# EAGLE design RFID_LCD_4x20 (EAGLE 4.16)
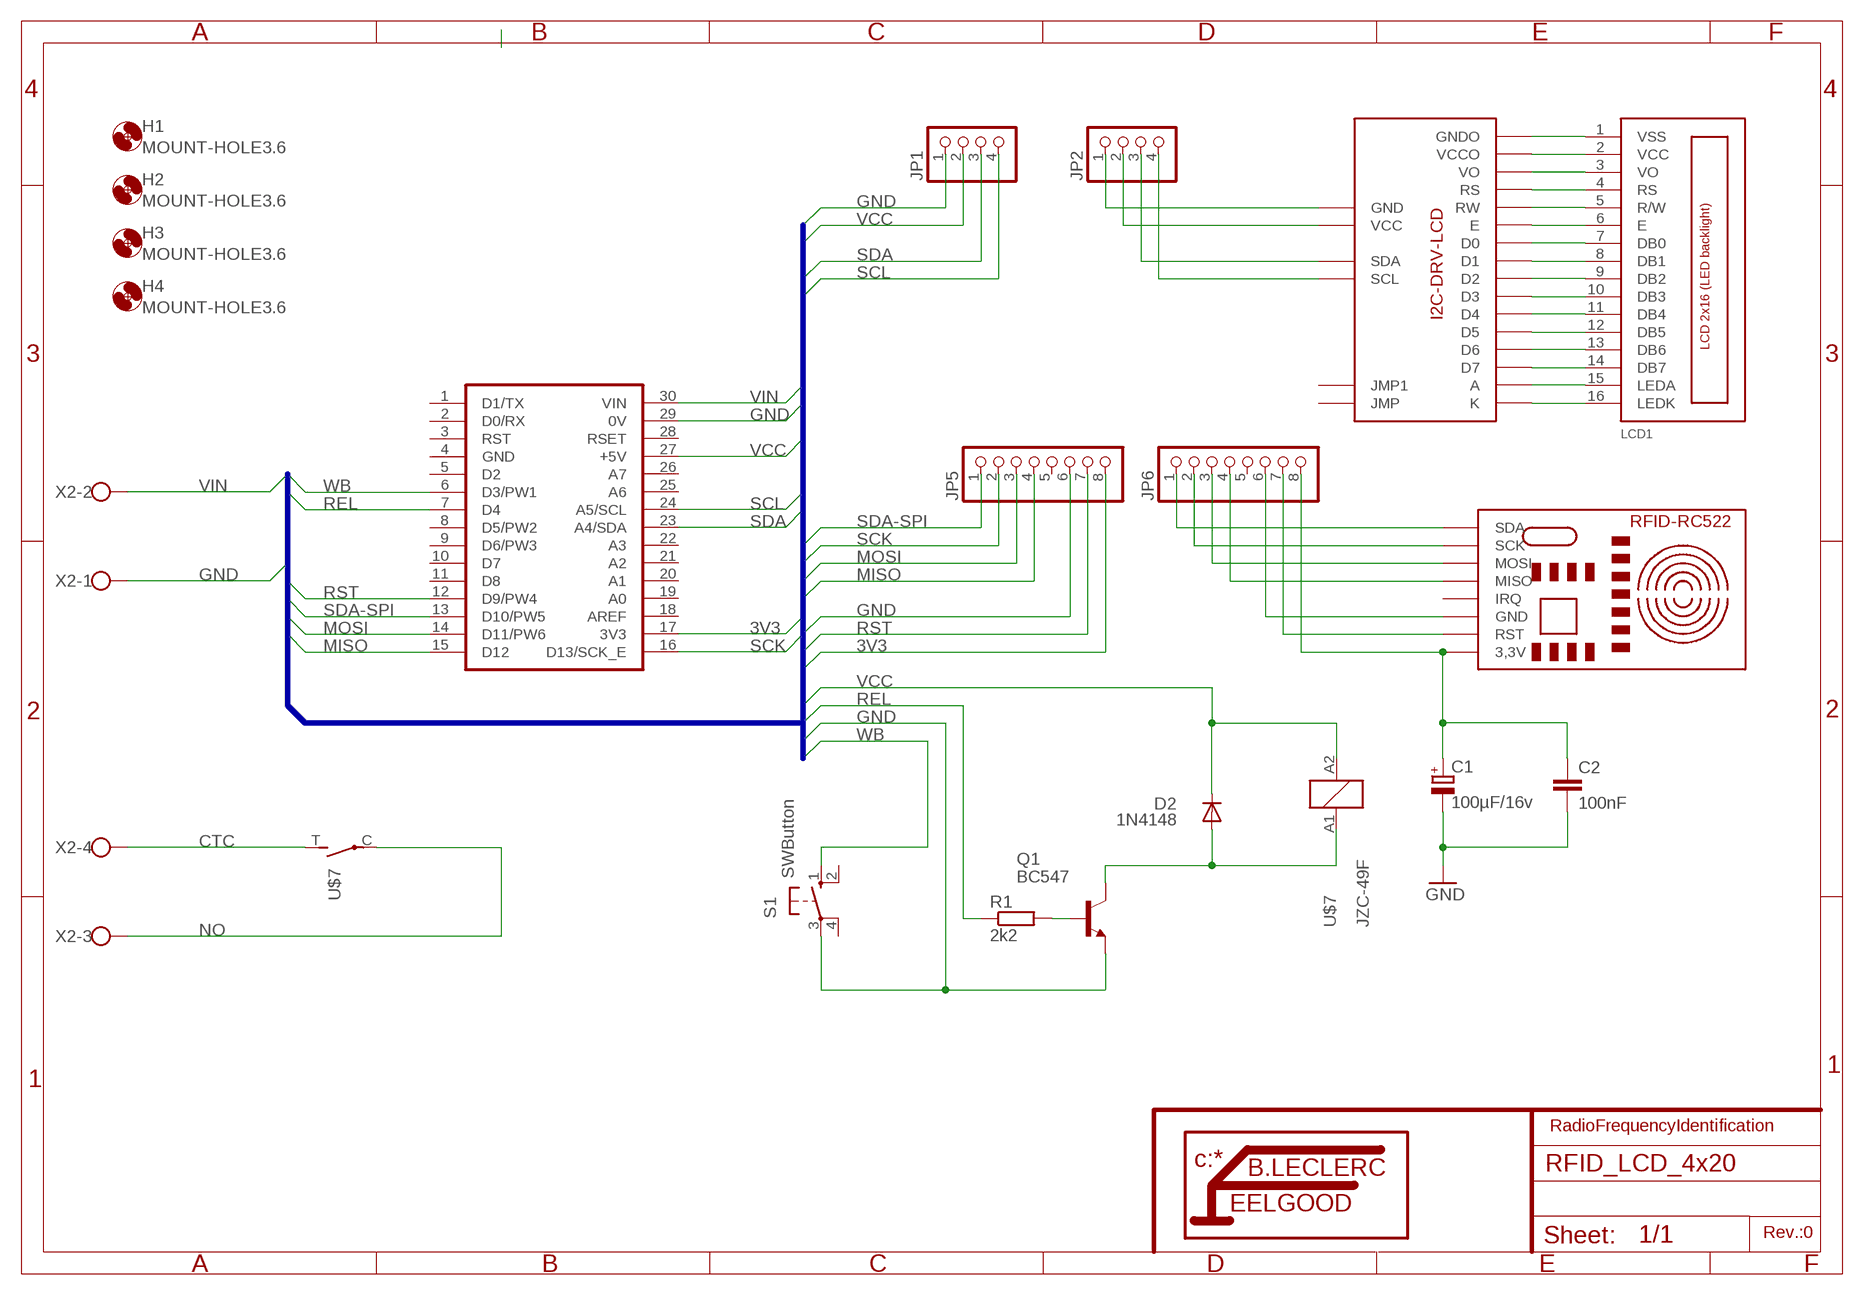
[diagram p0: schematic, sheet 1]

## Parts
C1  100µF/16v  CPOL-EUE2.5-5  [E2,5-5]
C2  100nF  C-EUC1206  [C1206]
D2  1N4148  DIODE-MINIMELF  [MINIMELF]
H1  MOUNT-HOLE3.6  [3,6]
H2  MOUNT-HOLE3.6  [3,6]
H3  MOUNT-HOLE3.6  [3,6]
H4  MOUNT-HOLE3.6  [3,6]
JP1  PINHD-1X4  [1X04]
JP2  PINHD-1X4  [1X04]
JP5  PINHD-1X8  [1X08]
JP6  PINHD-1X8  [1X08]
LCD1  LCD_2X16_SIL  [HY-1602F]
Q1  BC547  [TO92]
R1  2k2  R-EU_0309/12  [0309/12]
S1  SWButton  10-XX  [B3F-10XX]
U1  NANO  [NANO]
U$3  RFID-RC522  [RFID-RC522]
U$4  I2C-DRV-LCD  [I2C_DRV_LCD]
U$7  JZC-49F  [JZC-49F]
X2  W237-4  [W237-4]

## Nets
3V3: C1.+ C2.1 JP5.8 JP6.8 U1.17(3V3) U$3.3;3V(3,3V)
A1: D2.A Q1.3(C) U$7.A1
CTC: U$7.T(S) X2.4
GND: C1.- C2.2 JP1.1 JP2.1 JP5.6 JP6.6 Q1.1(E) S1.3(P) U1.29(0V) U$3.GND U$4.GND X2.1
MISO: JP5.4 JP6.4 U1.15(D12) U$3.MISO
MOSI: JP5.3 JP6.3 U1.14(D11/PW6) U$3.MOSI
N$3: LCD1.16(LEDK) U$4.K
N$4: LCD1.15(LEDA) U$4.A
N$6: LCD1.14(DB7) U$4.D7
N$7: JP2.4 U$4.SCL
N$8: LCD1.13(DB6) U$4.D6
N$9: LCD1.12(DB5) U$4.D5
N$10: Q1.2(B) R1.2
N$11: LCD1.11(DB4) U$4.D4
N$12: LCD1.10(DB3) U$4.D3
N$13: LCD1.9(DB2) U$4.D2
N$14: LCD1.8(DB1) U$4.D1
N$15: LCD1.7(DB0) U$4.D0
N$16: LCD1.6(E) U$4.E
N$17: LCD1.5(R/W) U$4.RW
N$18: LCD1.4(RS) U$4.RS
N$19: LCD1.3(VO) U$4.VO
N$20: LCD1.2(VCC) U$4.VCCO
N$21: LCD1.1(VSS) U$4.GNDO
N$27: JP6.7 U$3.RST
NO: U$7.C(P) X2.3
REL: R1.1 U1.7(D4)
RST: JP5.7 U1.12(D9/PW4)
SCK: JP5.2 JP6.2 U1.16(D13/SCK_E) U$3.SCK
SCL: JP1.4 U1.24(A5/SCL)
SDA: JP1.3 JP2.3 U1.23(A4/SDA) U$4.SDA
SDA-SPI: JP5.1 JP6.1 U1.13(D10/PW5) U$3.SDA
VCC: D2.C JP1.2 JP2.2 U1.27(+5V) U$4.VCC U$7.A2
VIN: U1.30(VIN) X2.2
WB: S1.1(S) U1.6(D3/PW1)
Unconnected: JP5.5 JP6.5 S1.2(S1) S1.4(P1) U1.1(D1/TX) U1.2(D0/RX) U1.3(RST) U1.5(D2) U1.8(D5/PW2) U1.9(D6/PW3) U1.10(D7) U1.11(D8) U1.18(AREF) U1.19(A0) U1.20(A1) U1.21(A2) U1.22(A3) U1.25(A6) U1.26(A7) U1.28(RSET) U$3.IRQ U$4.P$21(JMP) U$4.P$22(JMP1)

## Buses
B$1

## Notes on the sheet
- RadioFrequencyIdentification
- Rev.:0

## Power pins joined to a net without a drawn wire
GND: U1.4(GND)

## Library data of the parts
C1 = rcl:CPOL-EU: POLARIZED CAPACITOR, European symbol
C2 = rcl:C-EU: CAPACITOR, European symbol
D2 = diode:DIODE-: DIODE
H1-H4 = holes:MOUNT-HOLE: MOUNTING HOLE with drill center marker
JP1 JP2 = pinhead:PINHD-1X4: PIN HEADER
JP5 JP6 = pinhead:PINHD-1X8: PIN HEADER
LCD1 = lcd_2x16_led_backlight:LCD_2X16_SIL
Q1 = transistor-npn:BC547*: NPN Transistor
R1 = rcl:R-EU_: RESISTOR, European symbol
S1 = switch-omron:10-XX: OMRON SWITCH
U1 = Arduino:NANO
U$3 = Arduino:RFID-RC522
U$4 = Arduino:I2C-DRV-LCD
U$7 = relay:JZC-49F
X2 = con-wago-500:W237-4: WAGO SCREW CLAMP

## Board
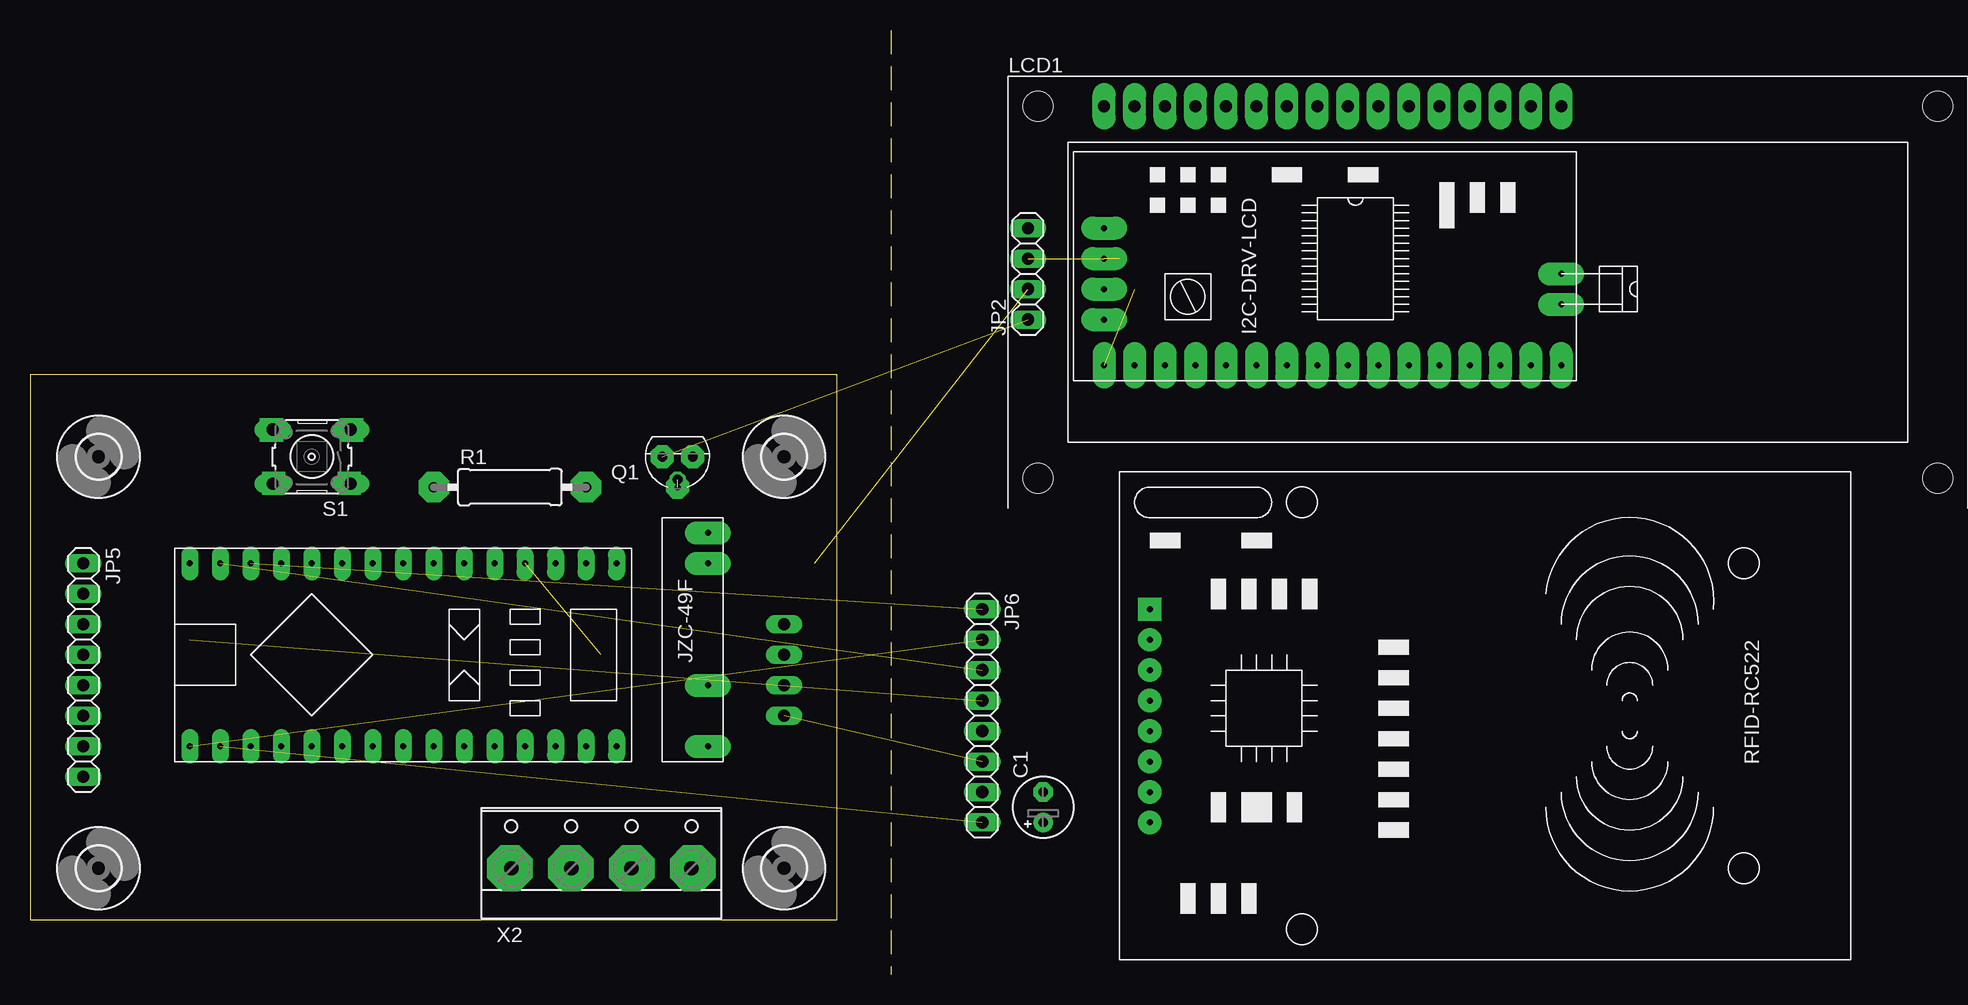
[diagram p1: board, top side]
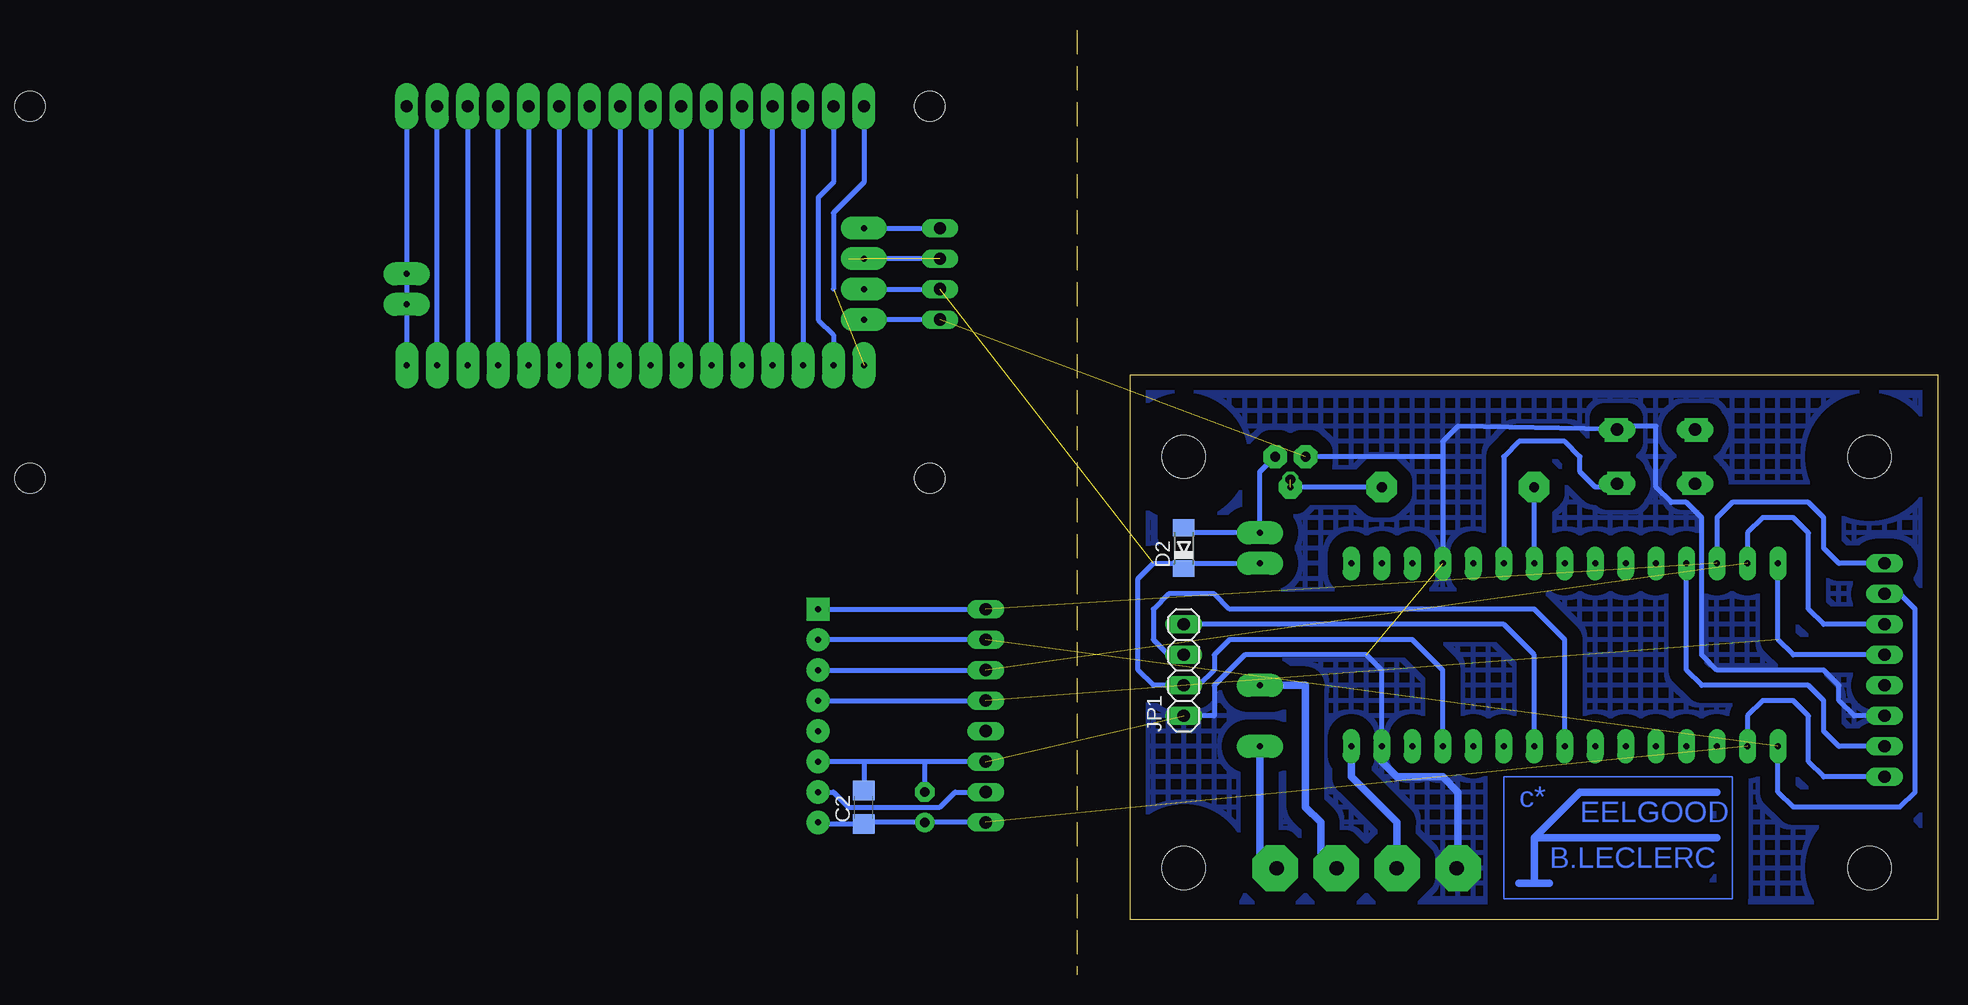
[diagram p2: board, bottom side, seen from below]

Size 71.75 x 78.74 mm. Coordinates in mm from the lower left corner, seen from the top.
Outline: 71.75,78.74 71.75,0
Outline: 0,4.61 67.29,4.61 67.29,50 0,50 0,4.61
Copper layers (1*16): Top 0.035mm / dielectric 1.5mm / Bottom 0.035mm
Design rules "default": minimum track width 10mil, minimum drill 24mil, track to track 8mil, track to pad 8mil, pad to pad 8mil, via to via 8mil, smd to smd 8mil, copper to edge 40mil, drill to drill 8mil, minimum pad ring 10mil, minimum via ring 8mil, stop-mask expansion 4mil, vias tented up to drill 0mil, thermal gap 10mil

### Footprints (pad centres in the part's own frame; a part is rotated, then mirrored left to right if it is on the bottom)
E2,5-5 = drill 0.813 pad 1.6 round: + -1.27,0 | drill 0.813 pad 1.6 octagon: - 1.27,0
C1206 = smd 1.6 x 1.8: 1 -1.4,0; 2 1.4,0
MINIMELF = smd 1.4 x 1.8: A 1.7,0; C -1.7,0
3,6 = hole 3.6: 0,0
1X04 = drill 1.016 long: 1 -3.81,0; 2 -1.27,0; 3 1.27,0; 4 3.81,0
1X08 = drill 1.016 long: 1 -8.89,0; 2 -6.35,0; 3 -3.81,0; 4 -1.27,0; 5 1.27,0; 6 3.81,0; 7 6.35,0; 8 8.89,0
HY-1602F = drill 1 pad 1.93 long: 1 2.54,0; 2 5.08,0; 3 7.62,0; 4 10.16,0; 5 12.7,0; 6 15.24,0; 7 17.78,0; 8 20.32,0; 9 22.86,0; 10 25.4,0; 11 27.94,0; 12 30.48,0; 13 33.02,0; 14 35.56,0; 15 38.1,0; 16 40.64,0 | hole 2.5: -2.96,0; 72.04,0; -2.96,-31; 72.04,-31
TO92 = drill 0.813 octagon: 1 1.27,0; 2 0,1.905; 3 -1.27,0
0309/12 = drill 0.813 octagon: 1 -6.35,0; 2 6.35,0
B3F-10XX = drill 1.016 long: 1 -3.251,2.261; 2 3.251,2.261; 3 -3.251,-2.261; 4 3.251,-2.261
NANO = drill 0.5 pad 1.422 long: 1 -7.62,17.78; 2 -7.62,15.24; 3 -7.62,12.7; 4 -7.62,10.16; 5 -7.62,7.62; 6 -7.62,5.08; 7 -7.62,2.54; 8 -7.62,0; 9 -7.62,-2.54; 10 -7.62,-5.08; 11 -7.62,-7.62; 12 -7.62,-10.16; 13 -7.62,-12.7; 14 -7.62,-15.24; 15 -7.62,-17.78; 16 7.62,-17.78; 17 7.62,-15.24; 18 7.62,-12.7; 19 7.62,-10.16; 20 7.62,-7.62; 21 7.62,-5.08; 22 7.62,-2.54; 23 7.62,0; 24 7.62,2.54; 25 7.62,5.08; 26 7.62,7.62; 27 7.62,10.16; 28 7.62,12.7; 29 7.62,15.24; 30 7.62,17.78
RFID-RC522 = drill 0.5 pad 1.93 round: 3;3V -27.94,-8.89; GND -27.94,-3.81; IRQ -27.94,-1.27; MISO -27.94,1.27; MOSI -27.94,3.81; RST -27.94,-6.35; SCK -27.94,6.35 | drill 0.5 pad 1.93 square: SDA -27.94,8.89
I2C_DRV_LCD = drill 0.5 pad 1.93 long: A 0,16.51; D0 0,-3.81; D1 0,-1.27; D2 0,1.27; D3 0,3.81; D4 0,6.35; D5 0,8.89; D6 0,11.43; D7 0,13.97; E 0,-6.35; GND -3.81,-19.05; GNDO 0,-19.05; K 0,19.05; P$21 -7.62,19.05; P$22 -5.08,19.05; RS 0,-11.43; RW 0,-8.89; SCL -11.43,-19.05; SDA -8.89,-19.05; VCC -6.35,-19.05; VCCO 0,-16.51; VO 0,-13.97
JZC-49F = drill 0.5 pad 1.93 long: A1 0,0; A2 2.54,0; C 12.7,0; T 17.78,0
W237-4 = drill 1.194 long: 1 -7.5,-1.27; 2 -2.5,-1.27; 3 2.5,-1.27; 4 7.5,-1.27

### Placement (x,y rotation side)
C1  84.45,13.97 90 top  (outside the outline)
C2  89.53,13.97 90 bottom  (outside the outline)
D2  62.86,35.56 90 bottom
H1  62.86,8.89 0 top
H2  5.71,8.89 0 top
H3  62.86,43.18 0 top
H4  5.71,43.18 0 top
JP1  62.86,25.4 90 bottom
JP2  83.18,58.42 90 top  (outside the outline)
JP5  4.44,25.4 270 top
JP6  79.37,21.59 270 top  (outside the outline)
LCD1  86.99,72.39 0 top  (outside the outline)
Q1  53.97,43.18 180 top
R1  40,40.64 0 top
S1  23.49,43.18 180 top
U1  31.11,26.67 270 top
U$2  [LITTFEEL]  33.65,3.81 0 bottom
U$3  121.28,21.59 0 top  (outside the outline)
U$4  108.58,50.8 270 top  (outside the outline)
U$7  56.51,36.83 270 top
X2  47.62,10.16 0 top

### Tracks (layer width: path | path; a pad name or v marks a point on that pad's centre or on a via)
3V3  (1 unrouted)
  Bottom 0.406: U1.17 15.87,21.59 14.6,22.86 12.06,22.86 10.79,21.59 10.79,17.78 9.52,16.51 JP5.8 | JP6.8 C1.+ 89.53,12.7 C2.1 93.21,12.57 U$3.3;3V
A1
  Bottom 0.406: D2.A 62.86,36.83 U$7.A1 56.51,41.91 Q1.3
CTC
  Bottom 0.61: U$7.T 56.51,8.89 X2.4
GND  (via drill 0.5, 0.5 pad 3.81)  (3 unrouted)
  Bottom 0.406: JP1.1 60.32,21.59 60.32,24.13 57.78,26.67 47.62,26.67 46.35,25.4 U1.29 | 41.27,43.18 Q1.1 | 41.27,43.18 U1.4 | 27.31,45.45 S1.3 | 27.31,45.45 40,45.72 41.27,44.45 41.27,43.18 | JP5.6 6.98,21.59 8.25,22.86 8.25,24.13 9.52,25.4 18.41,25.4 19.68,26.67 19.68,38.1 20.95,39.37 22.22,39.37 23.49,40.64 23.49,45.72 27.3,45.72 27.3,45.46 27.31,45.45 | JP2.1 U$4.GND | 89.53,15.24 C2.2 89.53,17.78 | JP6.6 84.45,17.78 | 84.45,17.78 89.53,17.78 | 89.53,17.78 U$3.GND | 84.45,17.78 C1.-
  Bottom 0.61: U1.29 46.35,17.78 45.08,16.51 41.27,16.51 40,15.24 v40,8.89 X2.1
  other vias: 62.86,21.59 4.44,21.59
  pour Bottom (isolate 1.27, no thermals, hatched): 0.63,49.53 66.67,49.53 66.67,5.08 0.63,5.08
MISO  (1 unrouted)
  Bottom 0.406: JP5.4 12.06,26.67 13.33,27.94 U1.15 | U$3.MISO JP6.4
MOSI  (1 unrouted)
  Bottom 0.406: JP5.3 9.52,29.21 10.79,30.48 10.79,36.83 12.06,38.1 14.6,38.1 15.87,36.83 U1.14 | U$3.MOSI JP6.3
N$1  (via drill 0.5)
  other vias: 4.44,29.21
N$2  (via drill 0.5)
  other vias: 4.44,26.67
N$3
  Bottom 0.406: LCD1.16 U$4.K
N$4
  Bottom 0.406: U$4.A LCD1.15
N$5  (via drill 0.5)
  other vias: 4.44,24.13
N$6
  Bottom 0.406: LCD1.14 U$4.D7
N$7
  Bottom 0.406: U$4.SCL JP2.4
N$8
  Bottom 0.406: U$4.D6 LCD1.13
N$9
  Bottom 0.406: LCD1.12 U$4.D5
N$10  (1 unrouted)
  Bottom 0.406: R1.2 53.97,40.64
N$11
  Bottom 0.406: LCD1.11 U$4.D4
N$12
  Bottom 0.406: LCD1.10 U$4.D3
N$13
  Bottom 0.406: LCD1.9 U$4.D2
N$14
  Bottom 0.406: LCD1.8 U$4.D1
N$15
  Bottom 0.406: LCD1.7 U$4.D0
N$16
  Bottom 0.406: U$4.E LCD1.6
N$17
  Bottom 0.406: LCD1.5 U$4.RW
N$18
  Bottom 0.406: U$4.RS LCD1.4
N$19
  Bottom 0.406: LCD1.3 U$4.VO
N$20
  Bottom 0.406: LCD1.2 92.07,66.04 93.34,64.77 93.34,54.61 92.07,53.34 U$4.VCCO
N$21  (1 unrouted)
  Bottom 0.406: LCD1.1 89.53,66.04 92.07,63.5 92.07,57.15
N$22  (via drill 0.5 pad 2.54)
  other vias: 33.65,40.64
N$23  (via drill 0.5)
  other vias: 4.44,19.05
N$24  (via drill 0.5)
  other vias: 4.44,16.51
N$25  (via drill 0.5)
  other vias: 62.86,29.21
N$26  (via drill 0.5)
  other vias: 62.86,26.67
N$27
  Bottom 0.406: U$3.RST 92.07,15.24 90.8,13.97 83.18,13.97 81.91,15.24 JP6.7
N$28  (via drill 0.5)
  other vias: 62.86,24.13
N$29  (via drill 0.5 pad 3.81)
  other vias: 45.08,8.89
N$30  (via drill 0.5)
  other vias: 4.44,31.75
N$31  (via drill 0.5)
  other vias: 4.44,34.29
N$32  (via drill 0.5 pad 3.81)
  other vias: 50.16,8.89
N$33  (via drill 0.5 pad 3.81)
  other vias: 55.24,8.89
N$34  (via drill 0.5 pad 2.54)
  other vias: 46.35,40.64
N$35  (via drill 0.5 pad 1.93)
  other vias: 52.7,43.18
N$36  (via drill 0.5 pad 1.93)
  other vias: 53.97,40.64
N$37  (via drill 0.5 pad 1.93)
  other vias: 55.24,43.18
N$38  (via drill 0.5 pad 1.93)
  other vias: 26.6,40.96
N$39  (via drill 0.5 pad 1.93)
  other vias: 26.79,45.4
N$40  (via drill 0.5 pad 1.93)
  other vias: 20.31,40.96
N$41  (via drill 0.5 pad 1.93)
  other vias: 20.12,45.4
NO
  Bottom 0.61: U$7.C 52.7,24.13 52.7,13.97 51.43,12.7 51.43,10.16 50.16,8.89 X2.3
REL
  Bottom 0.406: U1.7 R1.1
RST
  Bottom 0.406: JP5.7 8.25,19.05 9.52,20.32 9.52,22.86 10.79,24.13 19.68,24.13 20.95,25.4 U1.12
SCK  (1 unrouted)
  Bottom 0.406: U1.16 13.33,15.24 12.06,13.97 3.17,13.97 1.9,15.24 1.9,30.48 3.17,31.75 JP5.2 | JP6.2 U$3.SCK
SCL
  Bottom 0.406: U1.24 33.65,26.67 36.19,29.21 JP1.4
SDA  (2 unrouted)
  Bottom 0.406: U1.23 31.11,27.94 33.65,30.48 59.05,30.48 60.32,31.75 64.13,31.75 65.4,30.48 65.4,27.94 64.13,26.67 JP1.3 | JP2.3 90.8,59.69
SDA-SPI  (1 unrouted)
  Bottom 0.406: JP5.1 8.25,34.29 9.52,35.56 9.52,38.1 10.79,39.37 17.14,39.37 18.41,38.1 U1.13 | U$3.SDA JP6.1
VCC  (1 unrouted)
  Bottom 0.406: U1.27 41.27,25.4 43.81,27.94 59.05,27.94 60.32,26.67 60.32,25.4 61.59,24.13 JP1.2 65.4,24.13 66.67,25.4 66.67,33.02 65.4,34.29 62.86,34.29 | 56.94,33.86 U$7.A2 62.86,34.29 | 62.86,34.29 D2.C | U$4.VCC JP2.2 81.91,57.15
VIN
  Bottom 0.61: U1.30 48.89,16.51 45.08,12.7 45.08,8.89 | X2.2 45.08,8.89 | 45.08,8.89 45.08,7.62
WB
  Bottom 0.406: S1.1 27.02,40.64 28.57,40.64 29.84,41.91 29.84,43.18 31.11,44.45 34.92,44.45 36.19,43.18 U1.6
